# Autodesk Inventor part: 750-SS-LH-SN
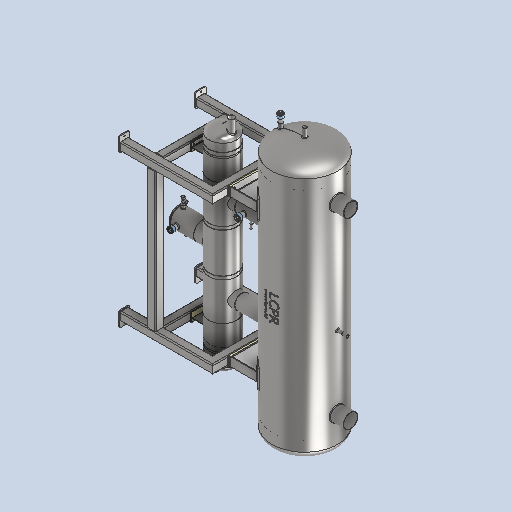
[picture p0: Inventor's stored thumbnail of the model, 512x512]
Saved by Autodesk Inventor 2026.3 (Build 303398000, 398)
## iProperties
Created: 2026-05
Part Number: 750-SS-LH-SN
Material: Generic
Document SubType Name: Modeling
Designer: rva
Density: 1 g/cm^3
Appearance: Default
Author: rva
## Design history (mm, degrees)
derived "LCPR-750-SS-LH-SN.iam"
body "Solid1"
node "LCPR-SS-750-2500-150-SN-WELD.iam:1::750 mm-SS-Dome End Cap.i"
node "LCPR-SS-750-2500-150-SN-WELD.iam:1::750 mm-SS-Dome End Cap.i"
node "LCPR-SS-750-2500-150-SN-WELD.iam:1::H1100-R.ipt:1"
node "LCPR-SS-750-2500-150-SN-WELD.iam:1::LCPR-750-SS-Leg-WELD.iam"
node "LCPR-SS-750-2500-150-SN-WELD.iam:1::LCPR-750-SS-Leg-WELD.iam"
node "LCPR-SS-750-2500-150-SN-WELD.iam:1::LCPR-LOGO.ipt:1"
node "LCPR-SS-750-2500-150-SN-WELD.iam:1::Welds"
node "Sub-SS-300-150-1940-110-75-65.iam:1::ISO 5251 Reducing Tee D"
node "Sub-SS-300-150-1940-110-75-65.iam:1::300-110-SS-Hole Sub Coo"
node "Sub-SS-300-150-1940-110-75-65.iam:1::300-110-SS-Hole Sub Coo"
node "Sub-SS-300-150-1940-110-75-65.iam:1::300 mm-SS-Subcooler Leg"
node "Sub-SS-300-150-1940-110-75-65.iam:1::300 mm-SS-Subcooler Leg"
node "Sub-SS-300-150-1940-110-75-65.iam:1::H1100-R.ipt:2"
node "Sub-SS-300-150-1940-110-75-65.iam:1::ISO 5251 Reducing Tee D"
node "Sub-SS-300-150-1940-110-75-65.iam:1::1-2 Inch NPT Socket - S"
node "Sub-SS-300-150-1940-110-75-65.iam:1::Welds"
node "Sub-SS-300-150-1940-110-75-65.iam:1::200 mm Oil Pot Assembly"
node "LPR-750-Frame Assembly.iam:1::LCPR-SS-750-170 x 120 Frame Fo"
node "LPR-750-Frame Assembly.iam:1::LCPR-SS-750-170 x 120 Frame Fo"
node "LPR-750-Frame Assembly.iam:1::LCPR-SS-750-170 x 120 Frame Fo"
node "LPR-750-Frame Assembly.iam:1::LCPR-SS-750-170 x 120 Frame Fo"
node "Nylon Heat Tranfer Spacer 640x100.ipt:1"
node "Nylon Heat Tranfer Spacer 640x100.ipt:2"
node "AS 1111 - M12 x 140.ipt:1"
node "AS 1112 (4) - Metric M12:1"
node "AS 1237 (4.2) 12 mm:1"
node "AS 1237 (4.2) 12 mm:2"
node "AS 1111 - M12 x 140.ipt:2"
node "AS 1112 (4) - Metric M12:2"
node "AS 1237 (4.2) 12 mm:3"
node "AS 1237 (4.2) 12 mm:4"
node "AS 1111 - M12 x 140.ipt:3"
node "AS 1112 (4) - Metric M12:3"
node "AS 1237 (4.2) 12 mm:5"
node "AS 1237 (4.2) 12 mm:6"
node "AS 1111 - M12 x 140.ipt:4"
node "AS 1112 (4) - Metric M12:4"
node "AS 1237 (4.2) 12 mm:7"
node "AS 1237 (4.2) 12 mm:8"
node "Welds"
node "Nylon Heat Tranfer Spacer 175x100.ipt:1"
node "Nylon Heat Tranfer Spacer 175x100.ipt:2"
node "LCPR-750-SS-LH-SN.iam_Bodies"
